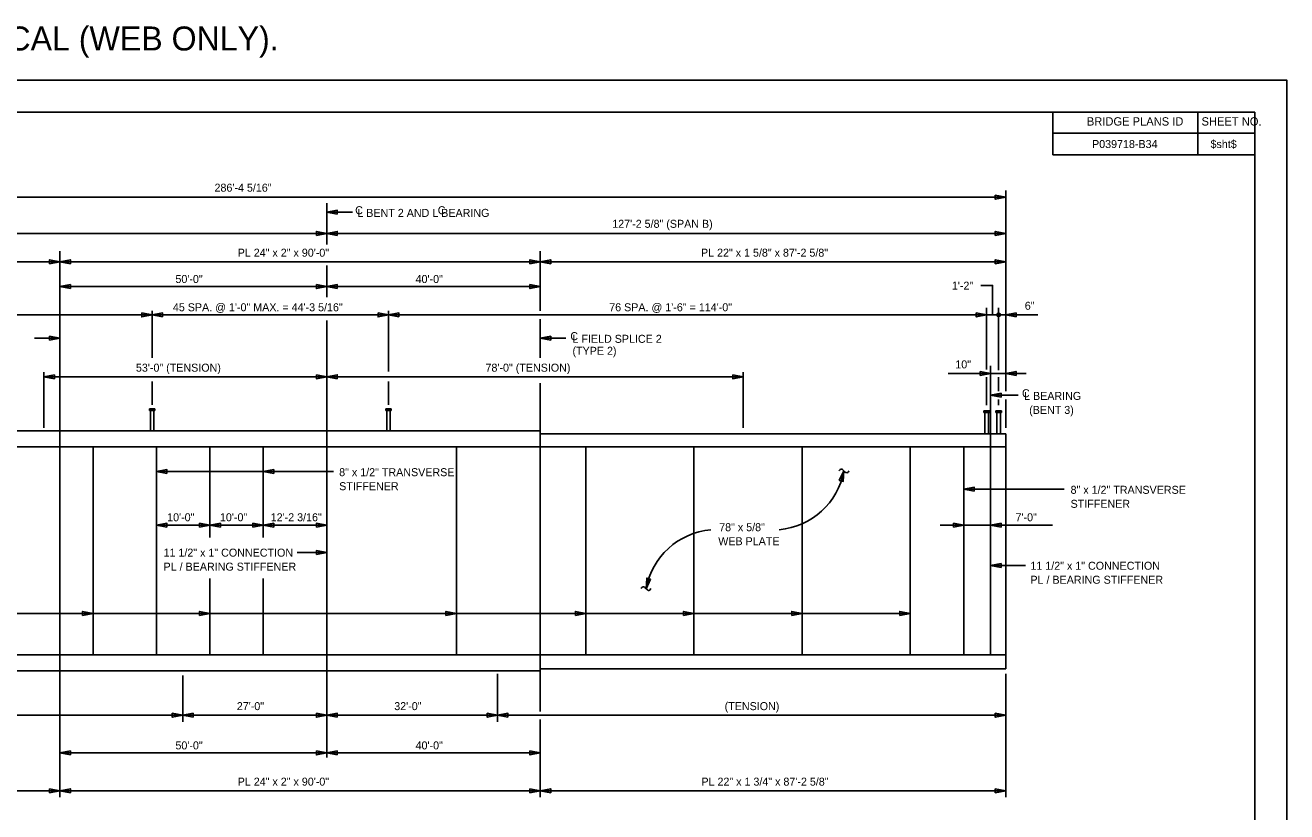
# Model space of a CAD drawing. Extents: x -383 to 11, y -361 to -94.
# Drawn here: x -240 to -161.2, y -145.2 to -96.1 of the extents above; entities that cross this region are included whole.
import ezdxf

# ---------------------------------------------------------------- set-up
doc = ezdxf.new("R2010")
doc.units = 0
for name, color, linetype in [('BR_AUTO DIMENSION', 7, 'Continuous'), ('BR_BORDER LINES', 7, 'Continuous'), ('BR_CENTER LINES', 7, 'Continuous'), ('BR_STRUCTURAL STEEL', 7, 'Continuous'), ('BR_TEXT', 7, 'Continuous'), ('Default', 7, 'Continuous'), ('Level 31', 7, 'Continuous')]:
    doc.layers.add(name, color=color, linetype=linetype)

msp = doc.modelspace()

# ---------------------------------------------------------------- linework, layer by layer
at = {"layer": 'BR_AUTO DIMENSION'}
for p, q in [((-274.182, -106.806), (-178.73, -106.806)), ((-178.73, -118.929), (-178.73, -106.393)), ((-221.135, -107.745), (-219.537, -107.745)), ((-274.182, -109.064), (-221.135, -109.064)), ((-221.135, -109.064), (-178.73, -109.064)), ((-257.802, -110.841), (-237.802, -110.841)), ((-237.802, -110.841), (-207.802, -110.841)), ((-207.802, -110.841), (-178.73, -110.841)), ((-221.135, -112.391), (-237.802, -112.391)), ((-207.802, -112.391), (-221.135, -112.391)), ((-272.515, -114.159), (-232.043, -114.159)), ((-232.043, -116.833), (-232.043, -113.909)), ((-232.043, -114.159), (-217.285, -114.159)), ((-217.285, -117.701), (-217.285, -113.909)), ((-217.285, -114.159), (-179.924, -114.159)), ((-179.924, -117.562), (-179.924, -113.71)), ((-176.721, -114.159), (-179.924, -114.159)), ((-179.174, -117.621), (-179.174, -113.71)), ((-237.802, -115.615), (-239.401, -115.615)), ((-207.802, -115.615), (-206.203, -115.615)), ((-238.802, -117.738), (-238.802, -121.213)), ((-238.802, -118.028), (-221.135, -118.028)), ((-195.135, -118.028), (-221.135, -118.028)), ((-195.135, -117.738), (-195.135, -121.213)), ((-182.328, -117.821), (-177.451, -117.821)), ((-179.924, -119.81), (-179.924, -118.048)), ((-179.174, -118.929), (-179.174, -118.048)), ((-232.043, -119.787), (-232.043, -118.317)), ((-217.285, -119.787), (-217.285, -118.317)), ((-179.674, -119.183), (-177.951, -119.183)), ((-179.174, -119.81), (-179.174, -119.447)), ((-178.73, -121.218), (-178.73, -119.447)), ((-231.769, -123.955), (-220.719, -123.955)), ((-181.341, -125.056), (-175.077, -125.056)), ((-175.816, -127.307), (-182.819, -127.307)), ((-221.135, -129.011), (-222.989, -129.011)), ((-179.674, -129.829), (-177.5, -129.829)), ((-184.696, -132.816), (-278.548, -132.816)), ((-230.135, -136.687), (-230.135, -139.586)), ((-210.469, -136.592), (-210.469, -139.586)), ((-178.73, -136.592), (-178.73, -144.298)), ((-230.135, -139.18), (-274.182, -139.18)), ((-221.135, -139.18), (-230.135, -139.18)), ((-210.469, -139.18), (-221.135, -139.18)), ((-178.73, -139.18), (-210.469, -139.18)), ((-221.135, -141.539), (-237.802, -141.539)), ((-207.802, -141.539), (-221.135, -141.539)), ((-257.802, -143.898), (-237.802, -143.898)), ((-237.802, -143.898), (-207.802, -143.898)), ((-207.802, -143.898), (-178.73, -143.898))]:
    msp.add_line(p, q, dxfattribs=at)
for points in [[(-179.38, -106.681), (-178.73, -106.806), (-179.38, -106.931)], [(-220.485, -107.87), (-221.135, -107.745), (-220.485, -107.62)], [(-221.785, -109.189), (-221.135, -109.064), (-221.785, -108.939)], [(-220.485, -109.189), (-221.135, -109.064), (-220.485, -108.939)], [(-179.38, -109.189), (-178.73, -109.064), (-179.38, -108.939)], [(-238.452, -110.966), (-237.802, -110.841), (-238.452, -110.716)], [(-237.152, -110.966), (-237.802, -110.841), (-237.152, -110.716)], [(-208.452, -110.966), (-207.802, -110.841), (-208.452, -110.716)], [(-207.152, -110.966), (-207.802, -110.841), (-207.152, -110.716)], [(-179.38, -110.966), (-178.73, -110.841), (-179.38, -110.716)], [(-237.152, -112.516), (-237.802, -112.391), (-237.152, -112.266)], [(-221.785, -112.266), (-221.135, -112.391), (-221.785, -112.516)], [(-220.485, -112.516), (-221.135, -112.391), (-220.485, -112.266)], [(-208.452, -112.266), (-207.802, -112.391), (-208.452, -112.516)], [(-232.693, -114.034), (-232.043, -114.159), (-232.693, -114.284)], [(-231.393, -114.284), (-232.043, -114.159), (-231.393, -114.034)], [(-217.935, -114.034), (-217.285, -114.159), (-217.935, -114.284)], [(-216.635, -114.284), (-217.285, -114.159), (-216.635, -114.034)], [(-180.574, -114.034), (-179.924, -114.159), (-180.574, -114.284)], [(-178.08, -114.284), (-178.73, -114.159), (-178.08, -114.034)], [(-238.452, -115.74), (-237.802, -115.615), (-238.452, -115.49)], [(-207.152, -115.74), (-207.802, -115.615), (-207.152, -115.49)], [(-238.152, -117.903), (-238.802, -118.028), (-238.152, -118.153)], [(-221.785, -117.903), (-221.135, -118.028), (-221.785, -118.153)], [(-220.485, -118.153), (-221.135, -118.028), (-220.485, -117.903)], [(-195.785, -117.903), (-195.135, -118.028), (-195.785, -118.153)], [(-180.324, -117.696), (-179.674, -117.821), (-180.324, -117.946)], [(-178.08, -117.946), (-178.73, -117.821), (-178.08, -117.696)], [(-179.024, -119.308), (-179.674, -119.183), (-179.024, -119.058)], [(-231.119, -124.08), (-231.769, -123.955), (-231.119, -123.83)], [(-224.452, -124.08), (-225.102, -123.955), (-224.452, -123.83)], [(-189.124, -124.504), (-188.842, -123.906), (-188.882, -124.566)], [(-180.691, -125.181), (-181.341, -125.056), (-180.691, -124.931)], [(-231.119, -127.432), (-231.769, -127.307), (-231.119, -127.182)], [(-229.085, -127.432), (-228.435, -127.307), (-229.085, -127.182)], [(-227.785, -127.432), (-228.435, -127.307), (-227.785, -127.182)], [(-225.752, -127.432), (-225.102, -127.307), (-225.752, -127.182)], [(-224.452, -127.432), (-225.102, -127.307), (-224.452, -127.182)], [(-221.785, -127.432), (-221.135, -127.307), (-221.785, -127.182)], [(-181.991, -127.432), (-181.341, -127.307), (-181.991, -127.182)], [(-179.024, -127.432), (-179.674, -127.307), (-179.024, -127.182)], [(-221.785, -129.136), (-221.135, -129.011), (-221.785, -128.886)], [(-179.024, -129.954), (-179.674, -129.829), (-179.024, -129.704)], [(-200.91, -130.673), (-201.193, -131.271), (-201.153, -130.611)], [(-236.386, -132.941), (-235.736, -132.816), (-236.386, -132.691)], [(-229.085, -132.941), (-228.435, -132.816), (-229.085, -132.691)], [(-213.695, -132.941), (-213.045, -132.816), (-213.695, -132.691)], [(-205.604, -132.941), (-204.954, -132.816), (-205.604, -132.691)], [(-198.851, -132.941), (-198.201, -132.816), (-198.851, -132.691)], [(-192.099, -132.941), (-191.449, -132.816), (-192.099, -132.691)], [(-185.346, -132.941), (-184.696, -132.816), (-185.346, -132.691)], [(-230.785, -139.055), (-230.135, -139.18), (-230.785, -139.305)], [(-229.485, -139.305), (-230.135, -139.18), (-229.485, -139.055)], [(-221.785, -139.055), (-221.135, -139.18), (-221.785, -139.305)], [(-220.485, -139.305), (-221.135, -139.18), (-220.485, -139.055)], [(-211.119, -139.055), (-210.469, -139.18), (-211.119, -139.305)], [(-209.819, -139.305), (-210.469, -139.18), (-209.819, -139.055)], [(-179.38, -139.055), (-178.73, -139.18), (-179.38, -139.305)], [(-237.152, -141.664), (-237.802, -141.539), (-237.152, -141.414)], [(-221.785, -141.414), (-221.135, -141.539), (-221.785, -141.664)], [(-220.485, -141.664), (-221.135, -141.539), (-220.485, -141.414)], [(-208.452, -141.414), (-207.802, -141.539), (-208.452, -141.664)], [(-238.452, -143.773), (-237.802, -143.898), (-238.452, -144.023)], [(-237.152, -144.023), (-237.802, -143.898), (-237.152, -143.773)], [(-208.452, -143.773), (-207.802, -143.898), (-208.452, -144.023)], [(-207.152, -144.023), (-207.802, -143.898), (-207.152, -143.773)], [(-179.38, -143.773), (-178.73, -143.898), (-179.38, -144.023)]]:
    msp.add_lwpolyline(points, close=True, dxfattribs=at)
msp.add_lwpolyline([(-179.549, -114.159), (-179.549, -112.317), (-180.289, -112.317)], dxfattribs=at)
msp.add_lwpolyline([(-179.549, -114.159), (-179.549, -112.317), (-180.289, -112.317)], dxfattribs=at)
msp.add_circle((-179.174, -114.159), 0.111, dxfattribs=at)
for centre, start, end in [((-193.266, -123.102), 274.96239, 349.7037), ((-196.769, -132.075), 94.96239, 169.7037)]:
    msp.add_arc(centre, 4.497, start, end, dxfattribs=at)
at = {"layer": 'BR_BORDER LINES'}
for p, q in [((-163.178, -101.489), (-297.843, -101.489)), ((-175.788, -104.156), (-175.788, -101.489)), ((-166.722, -104.156), (-166.722, -101.489)), ((-163.178, -185.489), (-163.178, -101.489)), ((-175.788, -102.808), (-163.178, -102.808)), ((-166.722, -102.808), (-163.178, -102.808)), ((-163.178, -104.156), (-175.788, -104.156))]:
    msp.add_line(p, q, dxfattribs=at)
at = {"layer": 'BR_CENTER LINES'}
for p, q in [((-221.135, -107.17), (-221.135, -109.769)), ((-237.802, -110.184), (-237.802, -144.298)), ((-207.802, -110.184), (-207.802, -113.912)), ((-221.135, -111.078), (-221.135, -113.059)), ((-221.135, -114.518), (-221.135, -122.412)), ((-207.802, -114.419), (-207.802, -116.846)), ((-179.674, -117.333), (-179.674, -122.412)), ((-207.802, -118.432), (-207.802, -138.953)), ((-221.135, -135.412), (-221.135, -141.826)), ((-207.802, -139.444), (-207.802, -144.298))]:
    msp.add_line(p, q, dxfattribs=at)
at = {"layer": 'BR_STRUCTURAL STEEL'}
for p, q in [((-257.802, -121.412), (-237.802, -121.412)), ((-237.802, -121.412), (-207.802, -121.412)), ((-237.802, -121.412), (-237.802, -122.412)), ((-207.802, -121.412), (-207.802, -122.412)), ((-207.802, -121.6), (-178.73, -121.6)), ((-178.73, -122.412), (-178.73, -121.6)), ((-274.182, -122.412), (-178.73, -122.412)), ((-235.736, -122.412), (-235.736, -135.412)), ((-231.769, -122.412), (-231.769, -135.412)), ((-228.435, -122.412), (-228.435, -128.076)), ((-225.102, -122.412), (-225.102, -128.076)), ((-221.135, -122.412), (-221.135, -135.412)), ((-213.045, -122.412), (-213.045, -135.412)), ((-204.954, -122.412), (-204.954, -135.412)), ((-198.201, -122.412), (-198.201, -135.412)), ((-191.449, -122.412), (-191.449, -135.412)), ((-184.696, -122.412), (-184.696, -135.412)), ((-181.341, -122.412), (-181.341, -135.412)), ((-179.674, -122.412), (-179.674, -135.412)), ((-178.73, -122.412), (-178.73, -135.412)), ((-231.769, -127.307), (-221.135, -127.307)), ((-228.435, -130.628), (-228.435, -135.412)), ((-225.102, -130.628), (-225.102, -135.412)), ((-274.182, -135.412), (-178.73, -135.412)), ((-237.802, -135.412), (-237.802, -136.412)), ((-207.802, -135.412), (-207.802, -136.412)), ((-178.73, -135.412), (-178.73, -136.287)), ((-207.802, -136.287), (-178.73, -136.287)), ((-257.802, -136.412), (-237.802, -136.412)), ((-237.802, -136.412), (-207.802, -136.412))]:
    msp.add_line(p, q, dxfattribs=at)
at = {"layer": 'BR_TEXT'}
for p, q in [((-189.102, -123.853), (-189.144, -123.914)), ((-188.76, -123.98), (-188.923, -123.831)), ((-188.527, -123.914), (-188.557, -123.96)), ((-201.508, -131.263), (-201.478, -131.217)), ((-201.275, -131.197), (-201.112, -131.346)), ((-200.933, -131.324), (-200.891, -131.263))]:
    msp.add_line(p, q, dxfattribs=at)
for centre, radius, start, end in [((-189.004, -123.906), 0.111, 43.45189, 151.73747), ((-188.666, -123.899), 0.125, 221.00704, 330.80591), ((-201.368, -131.278), 0.125, 41.00704, 150.80591), ((-201.031, -131.271), 0.111, 223.45189, 331.73747)]:
    msp.add_arc(centre, radius, start, end, dxfattribs=at)
at = {"layer": 'Default'}
for p, q in [((-232.215, -120.037), (-232.215, -120.131)), ((-232.215, -120.037), (-231.871, -120.037)), ((-232.215, -120.131), (-231.871, -120.131)), ((-232.152, -120.131), (-232.152, -121.412)), ((-231.933, -120.131), (-231.933, -121.412)), ((-231.871, -120.037), (-231.871, -120.131)), ((-217.457, -120.037), (-217.457, -120.131)), ((-217.457, -120.037), (-217.113, -120.037)), ((-217.457, -120.131), (-217.113, -120.131)), ((-217.395, -120.131), (-217.395, -121.412)), ((-217.176, -120.131), (-217.176, -121.412)), ((-217.113, -120.037), (-217.113, -120.131)), ((-180.096, -120.162), (-180.096, -120.256)), ((-180.096, -120.162), (-179.752, -120.162)), ((-180.096, -120.256), (-179.752, -120.256)), ((-180.033, -120.256), (-180.033, -121.537)), ((-179.815, -120.256), (-179.815, -121.537)), ((-179.752, -120.162), (-179.752, -120.256)), ((-179.346, -120.162), (-179.346, -120.256)), ((-179.346, -120.162), (-179.002, -120.162)), ((-179.346, -120.256), (-179.002, -120.256)), ((-179.283, -120.256), (-179.283, -121.537)), ((-179.065, -120.256), (-179.065, -121.537)), ((-179.002, -120.162), (-179.002, -120.256))]:
    msp.add_line(p, q, dxfattribs=at)
at = {"layer": 'Level 31'}
msp.add_lwpolyline([(-305.176, -187.489), (-161.176, -187.489), (-161.176, -99.489), (-305.176, -99.489)], close=True, dxfattribs=at)

# ---------------------------------------------------------------- texts
at = {"layer": 'BR_AUTO DIMENSION'}
for s, p in [('286\'-4 5/16"', (-228.148, -106.46)), ('127\'-2 5/8" (SPAN B)', (-203.307, -108.717)), ('PL 24" x 2" x 90\'-0"', (-226.701, -110.522)), ('PL 22" x 1 5/8" x 87\'-2 5/8"', (-197.764, -110.522)), ('50\'-0"', (-230.59, -112.166)), ('40\'-0"', (-215.59, -112.166)), ('1\'-2"', (-182.094, -112.585)), ('45 SPA. @ 1\'-0" MAX. = 44\'-3 5/16"', (-230.749, -113.933)), ('76 SPA. @ 1\'-6" = 114\'-0"', (-203.496, -113.933)), ('6"', (-177.539, -113.839)), (' 78\'-0" (TENSION)', (-211.409, -117.708)), ('10"', (-181.877, -117.502)), ('78" x 5/8" ', (-196.627, -127.678)), ('WEB PLATE', (-196.686, -128.553)), ('27\'-0"', (-226.757, -138.86)), ('(TENSION)', (-196.286, -138.86)), ('50\'-0"', (-230.59, -141.314)), ('40\'-0"', (-215.59, -141.314)), ('PL 24" x 2" x 90\'-0"', (-226.701, -143.579)), ('PL 22" x 1 3/4" x 87\'-2 5/8"', (-197.736, -143.579))]:
    msp.add_text(s, height=0.5, rotation=360, dxfattribs=at).set_placement(p)
for s, p in [(' 53\'-0" (TENSION)', (-233.243, -117.708)), ('10\'-0"', (-231.108, -127.057)), ('10\'-0"', (-227.809, -127.057)), ('12\'-2 3/16"', (-224.64, -127.057)), ('7\'-0"', (-178.118, -127.057)), ('32\'-0"', (-216.923, -138.86))]:
    msp.add_text(s, height=0.5, dxfattribs=at).set_placement(p)
at = {"layer": 'BR_TEXT'}
for s, height, p in [('EXAGGERATED BY 6 VERTICAL (FLANGES ONLY) AND BY 2 VERTICAL (WEB ONLY).', 1.5, (-305.065, -97.636)), ('BRIDGE PLANS ID', 0.52, (-173.663, -102.327)), ('SHEET NO.', 0.52, (-166.499, -102.327)), ('$sht$', 0.5, (-165.939, -103.732)), ('P039718-B34', 0.5, (-173.338, -103.732)), ('C', 0.5, (-177.716, -119.306)), ('L BEARING', 0.5, (-177.583, -119.473)), ('(BENT 3)', 0.5, (-177.265, -120.348)), ('11 1/2" x 1" CONNECTION ', 0.5, (-177.187, -130.086)), ('PL / BEARING STIFFENER', 0.5, (-177.187, -130.961))]:
    msp.add_text(s, height=height, dxfattribs=at).set_placement(p)
for s, p in [('C', (-219.363, -107.869)), ('L BENT 2 AND L BEARING', (-219.227, -108.035)), ('C', (-214.203, -107.869)), ('C', (-205.925, -115.739)), ('L FIELD SPLICE 2', (-205.79, -115.905)), ('(TYPE 2)', (-205.79, -116.655)), ('8" x 1/2" TRANSVERSE', (-220.363, -124.24)), ('STIFFENER', (-220.363, -125.115)), ('8" x 1/2" TRANSVERSE', (-174.679, -125.341)), ('STIFFENER', (-174.679, -126.216)), ('11 1/2" x 1" CONNECTION ', (-231.333, -129.268)), ('PL / BEARING STIFFENER', (-231.333, -130.143))]:
    msp.add_text(s, height=0.5, rotation=360, dxfattribs=at).set_placement(p)

doc.saveas('drawing.dxf')
